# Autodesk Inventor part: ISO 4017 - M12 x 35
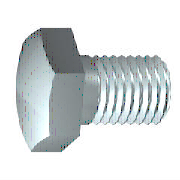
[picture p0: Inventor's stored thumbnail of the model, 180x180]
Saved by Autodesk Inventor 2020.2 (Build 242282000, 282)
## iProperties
Manager: www.cadconsulting.pl
Company: Fabian Stasiak CAD Consulting
IsCustomPart: 0
Created: 2010-02
Part Number: ISO 4017 - M12 x 35
Material: Stal, miękka
Description: Śruba z łbem sześciokątnym
Document SubType Name: Modeling
Standard: DIN EN 24 017
Designer: F.Stasiak
Standards Organization: DIN
Language: pl-PL
Size Designation: M12 x 35
Categories: <MemberInstance><Categories><Category DisplayName="Mocowania" InternalName="e4da775c-781d-43d5-af7c-5136215cf5a6" Mnemonic="FSTN"><Category DisplayName="Śruby"
Density: 1 g/cm^3
Appearance: Stal
Author: F.Stasiak
Subject: Zbiór ćwiczeń. Autodesk Inventor 2020. Kurs podstawowy
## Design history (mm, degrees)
sketch "Sketch1"
  geometry: L1 (0, 8.315)-(0, 6); L2 (5.3, 6)-(35, 6); L3 (35, 6)-(35, 0); L4 (35, 0)-(-0.6, 0); L5 (-7.72, 0)-(42.12, 0) reference; L6 (-0.6, 0)-(-0.6, 8.315); L7 (-0.6, 8.315)-(0, 8.315); L8 (5.3, 6)-(4.226, 6); L9 (4.226, 6)-(0, 6); L10 (0, -1.663)-(0, 9.978) reference
  constraints: 16 end point, 2 collinear, 2 perpendicular, 1 parallel
  dimensions: "d0" = 35 distance between parallel lines of L3 L1 (= NLG); "d1" = 29.7 distance from line of L2.start L3 (= GEL); "d2" = 12 diameter of L2 L4 (= GD); "d9" = 0.6001 distance between parallel lines of L6 L1 (computed from SD); "d10" = 16.63 diameter of L7 L4 (= SD2); "d13" = 1.07364 distance of L2.start L8.end (computed from GAL); "d14" = 12 diameter of L9 L4 (= BDM)
revolve "Body" sketch "Sketch1" stored, may be unused: angle "d12" = 90 deg
sketch "Sketch2"
  geometry: L1 (0, 10.392)-(9, 5.196); L2 (9, 5.196)-(9, -5.196); L3 (9, -5.196)-(0, -10.392); L4 (0, -10.392)-(-9, -5.196); L5 (-9, -5.196)-(-9, 5.196); L6 (-9, 5.196)-(0, 10.392); 2 further points
  constraints: 12 end point, 1 coincident, 1 vertical, 11 other
  dimensions: "d11" = 18 distance between parallel lines of L5 L2 (= SW)
extrude "Head" join sketch "Sketch2" distance "d3" = 6.9 (= KOH - SD); taper "d4" = 0 deg
sketch "Sketch4"
  geometry: L1 (-7.5, 9)-(-7.5, 10.392); L2 (-7.5, 10.392)-(-6.696, 10.392); L3 (-6.696, 10.392)-(-7.5, 9); L4 (-8.88, 0)-(0.78, 0) reference; L5 (-0.6, 10.392)-(-7.5, 10.392) reference; L6 (-7.5, 5.196)-(-7.5, 10.392) reference
  constraints: 6 end point, 2 collinear, 1 perpendicular, 1 vertical
  dimensions: "d5" = 30 deg angle of L3 L1 (= ANG1); "d19" = 18 diameter of L1.start L4 (= SW0)
revolve "Chamfer1" sketch "Sketch4" stored, may be unused: angle "d21" = 90 deg
feature "Thread" dims "d15" = 29.7 (= GEL), "d16" = 0
chamfer "Chamfer2" distance "d6" = 1.07354 (= -0.5 x SPD + 0.5 x GD); stored, may be unused: second distance "d7" = 1.07364 (computed from GUL), angle "d55" = 45 deg
workplane "Work Plane1"
body "Solid1"
other parameters: "NLG" = 35 [user parameter; used in 1 equation term], "GD" = 12 (= NND) [user parameter; used in 2 equation terms], "BDM" = 12 (= NND) [user parameter; used in 1 equation term], "KOH" = 7.5 [user parameter; used in 1 equation term], "GEL" = 29.7 [user parameter; used in 2 equation terms], "SW" = 18 [user parameter; used in 2 equation terms], "SW0" = 18 (= SW) [user parameter; used in 1 equation term], "SPD" = 9.85293 (= NND - 1.2269 x PTC) [user parameter; used in 1 equation term], "SD2" = 16.63 [user parameter; used in 2 equation terms], "SD" = 0.6 [user parameter; used in 2 equation terms], "ANG1" = 30 deg [user parameter; used in 1 equation term], "GAL" = 1.07354 (= 0.61345 x PTC) [user parameter; used in 1 equation term], "GUL" = 1.07354 (= 0.61345 x PTC) [user parameter; used in 1 equation term], "d8" = 0, "RR" = 0.6 [user parameter], "d57" = 0, "d58" = 0, "TPU" = 5.71429 (computed from PTC) [user parameter], "GD1" = 9.85293 (= THREADDIA - 1.2269 x PTC) [user parameter], "THREADDIA" = 12 [user parameter; used in 1 equation term], "SDH" = 16.63 (= SD2) [user parameter], "SDHG" = 5.3 [user parameter], "TOA" = 30 deg [user parameter], "PTC" = 1.75 [user parameter; used in 5 equation terms], "NND" = 12 [user parameter; used in 3 equation terms], "E0" = 20.79 [user parameter]
